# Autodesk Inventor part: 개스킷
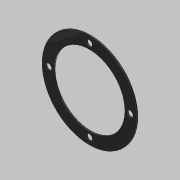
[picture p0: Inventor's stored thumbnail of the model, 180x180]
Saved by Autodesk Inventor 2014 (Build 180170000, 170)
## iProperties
Created: 2019-05
Part Number: 개스킷
Material: 고무
Document SubType Name: Modeling
Designer: mduedu
Density: 1 g/cm^3
Appearance: Rubber - Black - Version 1.1
Author: mduedu
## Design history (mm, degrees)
sketch "스케치1"
  geometry: C1 r 27 at (0, 0); C2 r 36 at (0, 0); 1 further point
  constraints: 2 centre point, 2 coincident
  dimensions: "d0" = 54 diameter of C1; "d1" = 72 diameter of C2
extrude "돌출1" new body sketch "스케치1" distance "d2" = 1; taper "d3" = 0 deg
sketch "스케치2" dims "d4" = 62
  geometry: C1 r 2.25 at (0, 31); 2 further points
  constraints: 2 vertical alignment, 1 centre point, 1 coincident, 2 other
  dimensions: "d5" = 4.5 diameter of C1
extrude "돌출2" cut sketch "스케치2" stored distance "d6" = 10; taper "d7" = 0 deg
node "솔리드1"
pattern_circular "원형 패턴1" dims angle "d9" = 360 deg
